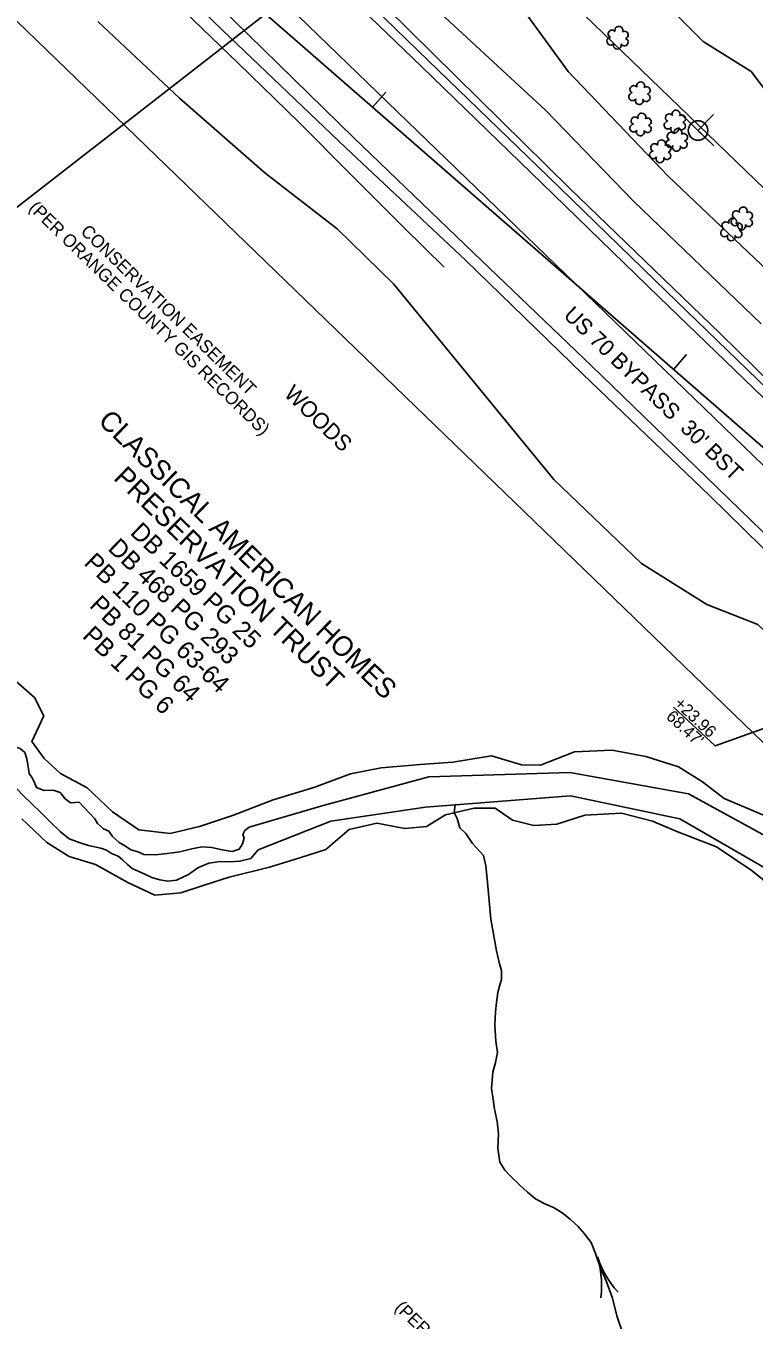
# Model space of a CAD drawing. Extents: x 1977096 to 1980486, y 845025 to 848427.
# Drawn here: x 1979154.9 to 1979337.4, y 845918.8 to 846243.1 of the extents above; entities that cross this region are included whole.
import ezdxf

# ---------------------------------------------------------------- set-up
doc = ezdxf.new("R2010")
doc.units = 0
for name, color, linetype in [('Exist Guardrail', 7, 'Continuous'), ('Exist Horizontal Alignment', 7, 'Continuous'), ('Exist Horizontal Baseline Alignment', 7, 'Continuous'), ('Exist Horizontal Baseline Alignment Tick small', 7, 'Continuous'), ('Exist Hydro Jurisdictional Stream or Body of Water', 7, 'Continuous'), ('Exist Hydro Stream Flow Arrow CELL', 7, 'Continuous'), ('Exist Hydro Stream or Body of Water', 7, 'Continuous'), ('Exist Property Deed Book Text', 7, 'Continuous'), ('Exist Property Owner Text', 7, 'Continuous'), ('Exist Property Same Owner Line CELL', 7, 'Continuous'), ('Exist Property Tie Line Leader', 7, 'Continuous'), ('Exist Property Tie Line Text', 7, 'Continuous'), ('Exist Right of Way Easement Line Text', 7, 'Continuous'), ('Exist Right of Way Line', 7, 'Continuous'), ('Exist Roads EOP', 7, 'Continuous'), ('Exist Roads EOT', 7, 'Continuous'), ('Exist Roads EOT Text', 7, 'Continuous'), ('Exist Utilities Power Joint Use Telephone CELL', 7, 'Continuous'), ('Exist Utilities Telephone UG Cable SUE LOS C', 7, 'Continuous'), ('Exist Vegetation Shrub CELL', 7, 'Continuous'), ('Exist Vegetation Woods Line', 7, 'Continuous'), ('Exist Vegetation Woods Line Text', 7, 'Continuous')]:
    doc.layers.add(name, color=color, linetype=linetype)

msp = doc.modelspace()

# ---------------------------------------------------------------- linework, layer by layer
at = {"layer": 'Exist Guardrail'}
msp.add_lwpolyline([(1979259.69, 846182.69), (1979249.62, 846192.61), (1979236.12, 846206.04), (1979223.28, 846219.01), (1979208.19, 846233.69), (1979190.05, 846251.2), (1979172.15, 846268.81), (1979158.61, 846281.9), (1979145.28, 846295.15), (1979131.93, 846308.01), (1979123.06, 846316.81), (1979114.36, 846325.76), (1979103.32, 846337.1), (1979096.34, 846344.2), (1979092.05, 846348.15)], dxfattribs=at)
at = {"layer": 'Exist Horizontal Alignment'}
msp.add_line((1978489.47, 846954.95), (1979491.73, 845985.98), dxfattribs=at)
at = {"layer": 'Exist Horizontal Baseline Alignment'}
msp.add_line((1978896.27, 846524.09), (1979767.77, 845764.02), dxfattribs=at)
at = {"layer": 'Exist Horizontal Baseline Alignment Tick small'}
for p, q in [((1979241.77, 846222.76), (1979245.05, 846226.53)), ((1979317.13, 846157.04), (1979320.42, 846160.8))]:
    msp.add_line(p, q, dxfattribs=at)
at = {"layer": 'Exist Hydro Jurisdictional Stream or Body of Water'}
for points in [[(1979151.81, 846062.65), (1979153.44, 846062), (1979154.6, 846061.02), (1979155.17, 846059.43), (1979155.44, 846057.5), (1979155.75, 846055.8), (1979156.5, 846054.7), (1979157.01, 846053.69), (1979157.6, 846052.3), (1979159.5, 846051.47), (1979161.77, 846051.56), (1979163.47, 846050.98), (1979164.73, 846049.44), (1979166.09, 846048.4), (1979168.23, 846048.57), (1979169.39, 846047.34), (1979170.89, 846045.72), (1979172.17, 846044.44), (1979172.83, 846043.26), (1979173.57, 846042.54), (1979174.36, 846041.94), (1979175.69, 846041.32), (1979175.69, 846041.32)], [(1979145.14, 846058.65), (1979145.14, 846058.65), (1979146.28, 846057.83), (1979147.09, 846057.06), (1979148.04, 846056.43), (1979149.44, 846055.53), (1979151.08, 846053.77), (1979152.57, 846051.98), (1979154.24, 846050.23), (1979156.43, 846048.14), (1979158.65, 846046.02), (1979160.89, 846043.77), (1979163.47, 846041.23), (1979165.75, 846039.39), (1979168.78, 846038.35), (1979170.62, 846037.72), (1979173.68, 846037.06)], [(1979210.85, 846042.28), (1979228.81, 846047.58), (1979255.87, 846054.94), (1979291.2, 846056)], [(1979291.2, 846056), (1979320.92, 846050.68)], [(1979320.92, 846050.68), (1979346.58, 846036.61), (1979363.12, 846024.9), (1979372.8, 846019.32)], [(1979213.13, 846036.66), (1979231.34, 846043.8), (1979255, 846047.3), (1979291.35, 846050.13)], [(1979291.35, 846050.13), (1979318.71, 846044.39), (1979343.06, 846030.4), (1979360.06, 846019.69), (1979376.65, 846012.09)], [(1979175.69, 846041.32), (1979176.59, 846039.99), (1979178.27, 846038.5), (1979179.84, 846037.59), (1979181.19, 846036.63)], [(1979181.19, 846036.63), (1979183.06, 846036.16), (1979184.46, 846035.44), (1979187.31, 846035.38), (1979190.3, 846035.73), (1979193.49, 846036.15), (1979196.47, 846036.86), (1979198.97, 846037.36), (1979201.46, 846037.25), (1979204.04, 846036.64), (1979206.58, 846036.25), (1979208.36, 846036.82), (1979209.19, 846038.11), (1979209.57, 846039.57), (1979209.22, 846040.49), (1979209.73, 846041.51), (1979210.85, 846042.28)], [(1979173.68, 846037.06), (1979175.07, 846036.59), (1979176.36, 846035.72), (1979178.01, 846035.03), (1979179.12, 846034.13)], [(1979179.12, 846034.13), (1979179.12, 846034.13), (1979180.34, 846032.98), (1979181.55, 846031.99), (1979183.02, 846031.27), (1979184.7, 846030.51), (1979186.44, 846029.68), (1979188.47, 846029.14), (1979190.43, 846028.79), (1979192.64, 846029.03), (1979195.63, 846030.49), (1979198, 846032.14), (1979200.76, 846033.32), (1979203.55, 846033.68), (1979205.97, 846033.64), (1979208.51, 846033.79), (1979211.23, 846034.5), (1979213.13, 846036.66)]]:
    msp.add_lwpolyline(points, dxfattribs=at)
at = {"layer": 'Exist Hydro Stream Flow Arrow CELL'}
msp.add_line((1979299.62, 845929.85), (1979299.62, 845929.85), dxfattribs=at)
for points in [[(1979303.3, 845925.77), (1979302.33, 845926.86), (1979301.46, 845928.08), (1979300.62, 845929.3), (1979299.9, 845930.55), (1979299.23, 845931.88), (1979298.63, 845933.25), (1979298.12, 845934.62)], [(1979298.94, 845924.39), (1979299.11, 845925.85), (1979299.12, 845927.35), (1979299.12, 845928.83), (1979298.99, 845930.27), (1979298.78, 845931.73), (1979298.49, 845933.2), (1979298.12, 845934.62)]]:
    msp.add_lwpolyline(points, dxfattribs=at)
at = {"layer": 'Exist Hydro Stream or Body of Water'}
msp.add_lwpolyline([(1979304.52, 845915.17), (1979303, 845919.86), (1979301.9, 845924.25), (1979300.31, 845928.66), (1979298.89, 845931.84), (1979297.59, 845935.51), (1979296.5, 845938.21), (1979294.82, 845940.43), (1979293.25, 845942.23), (1979291.26, 845944.12), (1979289.25, 845945.68), (1979287.24, 845946.96), (1979284.77, 845948.03), (1979282.55, 845949.15), (1979280.61, 845950.83), (1979278.66, 845952.63), (1979276.26, 845954.91), (1979274.92, 845956.34), (1979273.62, 845958.34), (1979273.14, 845961.85), (1979273.32, 845965.49), (1979273.01, 845968.52), (1979272.31, 845971.64), (1979271.98, 845974.18), (1979271.59, 845976.86), (1979271.9, 845980.93), (1979272.59, 845983.33), (1979273.05, 845985.88), (1979272.67, 845988.72), (1979272.43, 845992.68), (1979272.53, 845996.08), (1979272.78, 845998.36), (1979273.15, 846000.89), (1979273.68, 846002.82), (1979274.04, 846004.17), (1979274.03, 846006.41), (1979273.58, 846008.11), (1979272.83, 846011.3), (1979271.42, 846019.26), (1979270.91, 846024.8), (1979270.45, 846029.37), (1979270.13, 846032.62), (1979269.53, 846035.21), (1979266.82, 846038.26), (1979265.13, 846040.76), (1979263.64, 846042.14), (1979262.95, 846044.5), (1979262.2, 846045.97), (1979262.46, 846047.88)], dxfattribs=at)
at = {"layer": 'Exist Property Same Owner Line CELL'}
msp.add_lwpolyline([(1979292.37, 846303.36), (1979303.7, 846315.26), (1979077.67, 846139.38), (1979089, 846151.29)], dxfattribs=at)
at = {"layer": 'Exist Property Tie Line Leader'}
msp.add_lwpolyline([(1979368.94, 846077.48), (1979327.62, 846062.66), (1979317.19, 846072.42)], dxfattribs=at)
at = {"layer": 'Exist Right of Way Line'}
for p, q in [((1978524.22, 846990.9), (1979641.56, 845910.68)), ((1978965.22, 846425.46), (1979456.98, 845950.04))]:
    msp.add_line(p, q, dxfattribs=at)
at = {"layer": 'Exist Roads EOP'}
for points in [[(1979120.65, 846368.26), (1979133.49, 846352.99), (1979164.17, 846323.1), (1979194.73, 846293.87), (1979225.61, 846263.72), (1979255.68, 846234.45), (1979285.73, 846205.36), (1979315.37, 846176.53), (1979345.8, 846147.12), (1979377.72, 846116.63), (1979407.25, 846087.83), (1979438.13, 846057.9), (1979467.93, 846029.23), (1979498.8, 845999.18)], [(1979477.6, 845978.01), (1979446.84, 846007.88), (1979416.62, 846037.35), (1979386.7, 846066.33), (1979356.86, 846095.38), (1979326.24, 846125.39), (1979294.45, 846155.84), (1979265.05, 846184.42), (1979235.05, 846212.58), (1979204.24, 846241.97), (1979173.33, 846272.04), (1979142.8, 846301.86), (1979111.85, 846332.01), (1979093.06, 846348.31)]]:
    msp.add_lwpolyline(points, dxfattribs=at)
at = {"layer": 'Exist Roads EOT'}
for points in [[(1979131.83, 846351.23), (1979162.6, 846321.41), (1979193.04, 846291.89), (1979223.84, 846262.02), (1979254.08, 846232.84), (1979284.13, 846203.74), (1979313.6, 846175.13), (1979344.26, 846145.52), (1979376, 846114.94), (1979405.65, 846086.18), (1979436.21, 846056.39), (1979465.96, 846027.1), (1979496.86, 845997.11)], [(1979114.39, 846334.48), (1979145.37, 846304.35), (1979175.87, 846274.62), (1979206.9, 846244.54), (1979237.19, 846215.01), (1979267.05, 846186.27), (1979296.58, 846157.89), (1979328.22, 846127.36), (1979359.02, 846097.46), (1979388.76, 846068.61), (1979418.86, 846039.37), (1979449, 846010.07), (1979479.81, 845980.17)]]:
    msp.add_lwpolyline(points, dxfattribs=at)
at = {"layer": 'Exist Utilities Power Joint Use Telephone CELL'}
msp.add_line((1979323.3, 846216.89), (1979323.3, 846216.89), dxfattribs=at)
msp.add_lwpolyline([(1979319.04, 846221.03), (1979327.14, 846213.11), (1979323.28, 846216.88), (1979327.21, 846220.93)], dxfattribs=at)
msp.add_circle((1979323.3, 846216.9), 2.45, dxfattribs=at)
at = {"layer": 'Exist Utilities Telephone UG Cable SUE LOS C'}
msp.add_lwpolyline([(1979193.41, 846321.34), (1979192.65, 846320.39), (1979187.79, 846314.17), (1979186.96, 846308.83), (1979186.13, 846303.7), (1979221.88, 846270.8), (1979256.83, 846236.2), (1979291.06, 846202.44), (1979328.81, 846166.03), (1979367.53, 846128.09), (1979406.07, 846091.3), (1979445.38, 846052.99), (1979477.33, 846021.94)], dxfattribs=at)
at = {"layer": 'Exist Vegetation Shrub CELL'}
for p, q in [((1979303.23, 846239.98), (1979303.23, 846239.98)), ((1979308.7, 846226.06), (1979308.7, 846226.06)), ((1979308.99, 846218.22), (1979308.99, 846218.22)), ((1979317.58, 846218.97), (1979317.58, 846218.97)), ((1979318.03, 846214.35), (1979318.03, 846214.35)), ((1979313.92, 846211.51), (1979313.92, 846211.51)), ((1979334.38, 846194.69), (1979334.38, 846194.69)), ((1979331.75, 846191.93), (1979331.75, 846191.93))]:
    msp.add_line(p, q, dxfattribs=at)
for centre, radius, start, end in [((1979301.75, 846241.11), 0.968, 35.8908, 245.4216), ((1979303.46, 846242.02), 0.99, 334.8391, 200.4717), ((1979304.9, 846240.85), 0.929, 284.4567, 126.0861), ((1979301.43, 846239.28), 0.955, 95.1099, 327.9534), ((1979303.1, 846238.3), 0.984, 151.2797, 21.387), ((1979304.87, 846239.05), 0.937, 204.9913, 73.4601), ((1979308.93, 846228.1), 0.99, 334.8391, 200.4717), ((1979306.9, 846225.36), 0.955, 95.1099, 327.9534), ((1979307.22, 846227.19), 0.968, 35.8908, 245.4216), ((1979310.34, 846225.13), 0.937, 204.9913, 73.4601), ((1979310.38, 846226.93), 0.929, 284.4567, 126.0861), ((1979308.58, 846224.38), 0.984, 151.2797, 21.387), ((1979307.51, 846219.34), 0.968, 35.8908, 245.4216), ((1979309.22, 846220.26), 0.99, 334.8391, 200.4717), ((1979310.66, 846219.08), 0.929, 284.4567, 126.0861), ((1979315.78, 846218.26), 0.955, 95.1099, 327.9534), ((1979316.1, 846220.1), 0.968, 35.8908, 245.4216), ((1979317.81, 846221.01), 0.99, 334.8391, 200.4717), ((1979319.25, 846219.84), 0.929, 284.4567, 126.0861), ((1979307.19, 846217.51), 0.955, 95.1099, 327.9534), ((1979308.86, 846216.53), 0.984, 151.2797, 21.387), ((1979310.63, 846217.29), 0.937, 204.9913, 73.4601), ((1979316.55, 846215.48), 0.968, 35.8908, 245.4216), ((1979317.45, 846217.29), 0.984, 151.2797, 21.387), ((1979318.26, 846216.39), 0.99, 334.8391, 200.4717), ((1979319.22, 846218.04), 0.937, 204.9913, 73.4601), ((1979319.71, 846215.22), 0.929, 284.4567, 126.0861), ((1979312.43, 846212.63), 0.968, 35.8908, 245.4216), ((1979314.15, 846213.55), 0.99, 334.8391, 200.4717), ((1979315.59, 846212.38), 0.929, 284.4567, 126.0861), ((1979316.23, 846213.65), 0.955, 95.1099, 327.9534), ((1979317.9, 846212.67), 0.984, 151.2797, 21.387), ((1979319.67, 846213.42), 0.937, 204.9913, 73.4601), ((1979312.12, 846210.8), 0.955, 95.1099, 327.9534), ((1979313.79, 846209.82), 0.984, 151.2797, 21.387), ((1979315.55, 846210.58), 0.937, 204.9913, 73.4601), ((1979332.89, 846195.81), 0.968, 35.8908, 245.4216), ((1979334.61, 846196.73), 0.99, 334.8391, 200.4717), ((1979336.05, 846195.56), 0.929, 284.4567, 126.0861), ((1979330.27, 846193.06), 0.968, 35.8908, 245.4216), ((1979331.98, 846193.97), 0.99, 334.8391, 200.4717), ((1979332.58, 846193.98), 0.955, 95.1099, 327.9534), ((1979333.42, 846192.8), 0.929, 284.4567, 126.0861), ((1979334.25, 846193), 0.984, 151.2797, 21.387), ((1979336.01, 846193.76), 0.937, 204.9913, 73.4601), ((1979329.95, 846191.23), 0.955, 95.1099, 327.9534), ((1979331.62, 846190.25), 0.984, 151.2797, 21.387), ((1979333.38, 846191), 0.937, 204.9913, 73.4601)]:
    msp.add_arc(centre, radius, start, end, dxfattribs=at)
at = {"layer": 'Exist Vegetation Woods Line'}
for points in [[(1979285.06, 846221.98), (1979252.33, 846252.35), (1979231.85, 846273.63), (1979213.75, 846291.36), (1979202.59, 846304.76), (1979202.01, 846315.27), (1979213.14, 846306.77), (1979230.39, 846303.01), (1979247.97, 846286.7), (1979265.81, 846266.31), (1979276.02, 846252.06), (1979290.77, 846231.67)], [(1979543.34, 846021.41), (1979527.72, 846037.66), (1979513.46, 846051.26), (1979497.57, 846064.79), (1979478.75, 846087.72), (1979460.41, 846100.3), (1979446.88, 846119.85), (1979428.53, 846139.1), (1979409.31, 846160.93), (1979389.73, 846179.91), (1979378.35, 846196.2), (1979359.39, 846203.8), (1979346.56, 846218.58), (1979336.63, 846231.68), (1979324.62, 846239.2), (1979312.41, 846251.59)], [(1979172.92, 846244.25), (1979193.4, 846225.03), (1979214.73, 846206.31), (1979232.92, 846192.26), (1979246.97, 846178.48)], [(1979290.77, 846231.67), (1979315.79, 846205.44), (1979345.79, 846177.01)], [(1979339.13, 846168.45), (1979307.17, 846199.2), (1979285.06, 846221.98)], [(1979246.97, 846178.48), (1979287.2, 846129.48), (1979309.1, 846108.38), (1979325.54, 846098.15), (1979338.27, 846093.08), (1979356.75, 846075.44), (1979374.46, 846058.56), (1979392.79, 846040.61), (1979412.21, 846019.31), (1979430.21, 846002.17), (1979452.41, 845983.55), (1979466.05, 845973.85), (1979479.14, 845959.16), (1979493.86, 845943.93), (1979507.18, 845932.34)], [(1979340.1, 846045.18), (1979329.87, 846049.54), (1979324.45, 846053.7), (1979318.37, 846057.4), (1979310.22, 846060.03), (1979301.83, 846061.6), (1979292.34, 846061.22), (1979283.84, 846057.86), (1979279.04, 846057.97), (1979271.53, 846060.18), (1979261.83, 846058.63), (1979253.67, 846058.04), (1979243.95, 846057.15), (1979236.2, 846055.68), (1979227.29, 846052.33), (1979216.88, 846049.14), (1979206.91, 846045.35), (1979198.38, 846042.49), (1979191.04, 846040.7), (1979183.18, 846041.63), (1979176.59, 846046.15), (1979170.27, 846052.17), (1979163.6, 846055.78), (1979159.52, 846059.54), (1979156.36, 846063.77), (1979159.39, 846070.25), (1979157.06, 846074.84), (1979152.36, 846078.92)], [(1979153.88, 846044.44), (1979160.12, 846038.5), (1979165.71, 846034.94), (1979172.37, 846032.94), (1979180.44, 846028.43), (1979187.18, 846025.3), (1979193.69, 846025.88), (1979199.58, 846027.76), (1979205.83, 846029.78), (1979215.91, 846032.31), (1979223.55, 846034.6), (1979230.09, 846036.71), (1979235.88, 846041.77), (1979242.83, 846043.34), (1979249.84, 846041.96), (1979255.31, 846042.49), (1979260.04, 846045.45), (1979267.19, 846047.12), (1979272.48, 846047.08), (1979276.8, 846044.04), (1979282.16, 846042.74), (1979287.9, 846043.03), (1979294.92, 846045.29), (1979304.14, 846045.86), (1979311.88, 846043.85), (1979318.43, 846041.03), (1979327.91, 846037.35), (1979336.6, 846031.57), (1979343.94, 846025.72)]]:
    msp.add_lwpolyline(points, dxfattribs=at)

# ---------------------------------------------------------------- texts
at = {"layer": 'Exist Property Deed Book Text'}
for s, p in [('DB 1659 PG 25', (1979180.8, 846115.9)), ('DB 468 PG 293', (1979175.2, 846111.92)), ('PB 110 PG 63-64', (1979169.24, 846108.28)), ('PB 81 PG 64', (1979170.59, 846097.62)), ('PB 1 PG 6', (1979168.82, 846089.96))]:
    msp.add_text(s, height=4.5, rotation=316.1019, dxfattribs=at).set_placement(p)
at = {"layer": 'Exist Property Owner Text'}
for s, p in [('CLASSICAL AMERICAN HOMES', (1979172.76, 846143.8)), ('PRESERVATION TRUST', (1979176.65, 846129.6))]:
    msp.add_text(s, height=5, rotation=315.9214, dxfattribs=at).set_placement(p)
at = {"layer": 'Exist Property Tie Line Text'}
for s, p in [('+23.96', (1979317.13, 846072.99)), ("68.47'", (1979315.1, 846069.75))]:
    msp.add_text(s, height=3, rotation=316.9589, dxfattribs=at).set_placement(p)
at = {"layer": 'Exist Right of Way Easement Line Text'}
for s, p in [('(PER ORANGE COUNTY GIS RECORDS)', (1979155.43, 846197.25)), ('CONSERVATION EASEMENT', (1979168.41, 846191.34)), ('(PER ORANGE COUNTY GIS RECORDS)', (1979247.11, 845921.65))]:
    msp.add_text(s, height=3.2, rotation=315.8475, dxfattribs=at).set_placement(p)
at = {"layer": 'Exist Roads EOT Text'}
msp.add_text("US 70 BYPASS  30' BST", height=4, rotation=315.919, dxfattribs=at).set_placement((1979289.36, 846170.32))
at = {"layer": 'Exist Vegetation Woods Line Text'}
msp.add_text('WOODS', height=4, rotation=315.6543, dxfattribs=at).set_placement((1979219.35, 846150.63))

doc.saveas('drawing.dxf')
